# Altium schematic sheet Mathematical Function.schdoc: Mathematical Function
size A4; Organization: Altium Limited; Address1: L3, 12a Rodborough Rd; Address2: Frenchs Forest; Address3: NSW; Address4: Australia 2086; DocumentNumber: 1; SheetNumber: 1; SheetTotal: 1
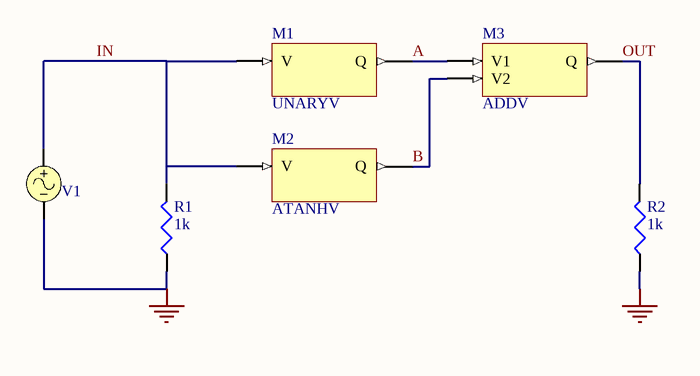
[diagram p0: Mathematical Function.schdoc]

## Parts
M1  UNARYV
M2  ATANHV
M3  ADDV
R1  1k
R2  1k
V1  VSIN  (value not drawn)

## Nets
GND: R1.2(BOT) R2.2(BOT) V1.2
A: M1.2(Q) M3.1(V1)
B: M2.2(Q) M3.2(V2)
IN: M1.1(V) M2.1(V) R1.1(TOP) V1.1
OUT: M3.3(Q) R2.1(TOP)

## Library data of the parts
M1 = UNARYV: Unary - of Voltage
M2 = ATANHV: Hyperbolic Arc Tangent of Voltage
M3 = ADDV: Add Voltages
R1 R2 = RES: Resistor
V1 = VSIN: Sinusoidal Voltage Source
